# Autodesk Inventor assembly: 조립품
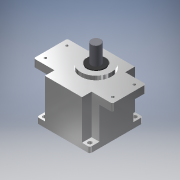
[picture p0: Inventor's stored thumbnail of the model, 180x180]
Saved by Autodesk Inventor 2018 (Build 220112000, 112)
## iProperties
Created: 2020-07
Part Number: 조립품
Material: 일반
Document SubType Name: Assembly
Designer: Admin
Author: Admin
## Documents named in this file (10)
- C:\Users\Admin\Desktop\700707V1013\조립품.iam
- C:\Users\Admin\Desktop\700707V1013\본체.ipt
- C:\Users\Admin\Desktop\700707V1013\커버.ipt
- C:\Users\Admin\Desktop\700707V1013\서브 축.ipt
- C:\Users\Admin\Desktop\700707V1013\베어링 6003.ipt
- C:\Users\Admin\Desktop\700707V1013\베어링 608.ipt
- C:\Users\Admin\Desktop\700707V1013\메인 축.ipt
- C:\Users\Admin\Desktop\700707V1013\오일 실 8 22 7.ipt
- C:\Users\Admin\Desktop\700707V1013\오일 실 17 32 8.ipt
- C:\Users\Admin\Desktop\700707V1013\볼트 M4.ipt
